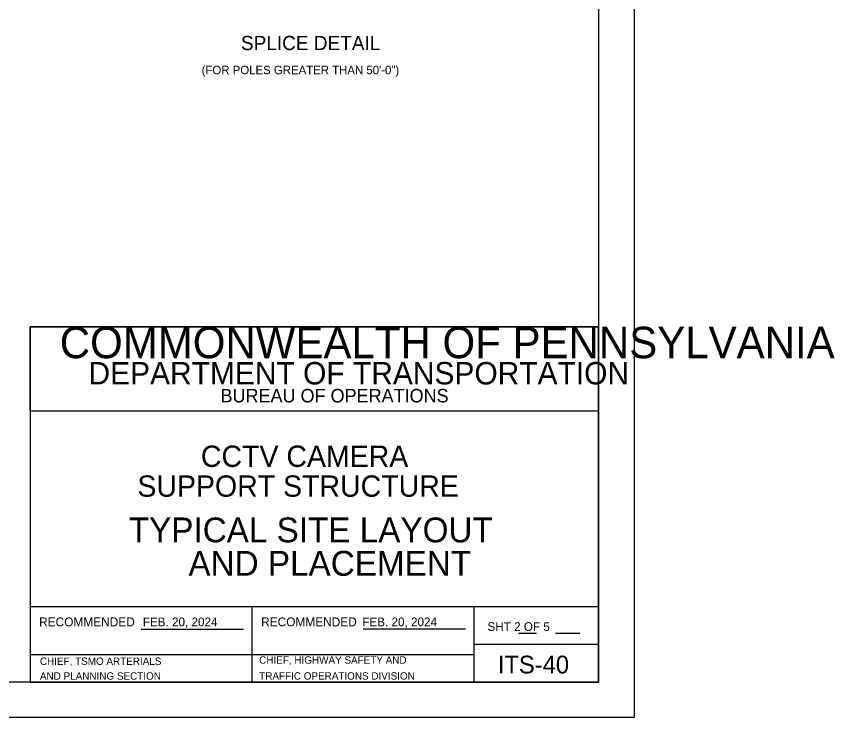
# Model space of a CAD drawing. Extents: x 1299104.8 to 1299141.6, y 239639.8 to 239661.8.
# Drawn here: x 1299130.11 to 1299141.62, y 239639.79 to 239649.66 of the extents above; entities that cross this region are included whole.
import ezdxf

# ---------------------------------------------------------------- set-up
doc = ezdxf.new("R2010")
doc.units = 0
for name, color, linetype in [('1', 7, 'Continuous'), ('2', 7, 'Continuous'), ('DIM TXT', 7, 'Continuous'), ('GS_plotshape_p', 7, 'Continuous'), ('Level 1', 7, 'Continuous'), ('PTEXT', 7, 'Continuous')]:
    doc.layers.add(name, color=color, linetype=linetype)

msp = doc.modelspace()

# ---------------------------------------------------------------- linework, layer by layer
at = {"layer": '1'}
for p, q in [((1299131.864, 239641.035), (1299133.302, 239641.035)), ((1299134.989, 239641.043), (1299136.427, 239641.043)), ((1299130.302, 239640.68), (1299133.427, 239640.68))]:
    msp.add_line(p, q, dxfattribs=at)
at = {"layer": 'DIM TXT'}
msp.add_line((1299138.802, 239639.791), (1299138.802, 239639.791), dxfattribs=at)
at = {"layer": 'GS_plotshape_p'}
msp.add_lwpolyline([(1299104.802, 239661.791), (1299138.802, 239661.791), (1299138.802, 239639.791), (1299104.802, 239639.791)], close=True, dxfattribs=at)
at = {"layer": 'Level 1'}
for p, q in [((1299130.302, 239641.354), (1299138.302, 239641.354)), ((1299133.427, 239640.291), (1299133.427, 239641.354)), ((1299136.552, 239640.291), (1299136.552, 239641.354)), ((1299137.177, 239640.979), (1299137.427, 239640.979)), ((1299137.694, 239640.981), (1299138.038, 239640.981)), ((1299136.552, 239640.823), (1299138.302, 239640.823)), ((1299133.427, 239640.68), (1299136.552, 239640.68))]:
    msp.add_line(p, q, dxfattribs=at)
for points in [[(1299138.302, 239640.291), (1299106.302, 239640.291), (1299106.302, 239661.291), (1299138.302, 239661.291)], [(1299130.302, 239640.291), (1299138.302, 239640.291), (1299138.302, 239645.291), (1299130.302, 239645.291)], [(1299130.302, 239645.291), (1299138.302, 239645.291), (1299138.302, 239644.104), (1299130.302, 239644.104)]]:
    msp.add_lwpolyline(points, close=True, dxfattribs=at)

# ---------------------------------------------------------------- texts
at = {"layer": '1'}
for s, height, p in [('COMMONWEALTH OF PENNSYLVANIA', 0.44223, (1299130.717, 239644.85)), ('DEPARTMENT OF TRANSPORTATION', 0.31514, (1299131.122, 239644.481)), ('BUREAU OF OPERATIONS', 0.18955, (1299132.98, 239644.228)), ('RECOMMENDED', 0.125, (1299130.427, 239641.076)), ('FEB. 20, 2024', 0.12303, (1299131.886, 239641.077)), ('RECOMMENDED', 0.125, (1299133.552, 239641.076)), ('FEB. 20, 2024', 0.12303, (1299134.976, 239641.077)), ('CHIEF, TSMO ARTERIALS ', 0.10417, (1299130.438, 239640.533)), ('CHIEF, HIGHWAY SAFETY AND ', 0.10417, (1299133.525, 239640.55)), ('TRAFFIC OPERATIONS DIVISION', 0.10417, (1299133.525, 239640.326)), ('AND PLANNING SECTION', 0.10417, (1299130.438, 239640.325))]:
    msp.add_text(s, height=height, dxfattribs=at).set_placement(p)
at = {"layer": '2'}
msp.add_text('SHT 2 OF 5', height=0.123, dxfattribs=at).set_placement((1299136.738, 239641.011))
at = {"layer": 'DIM TXT'}
for s, height, p in [('SPLICE DETAIL', 0.2, (1299133.268, 239649.186)), ('(FOR POLES GREATER THAN 50\'-0")', 0.12, (1299132.715, 239648.846))]:
    msp.add_text(s, height=height, dxfattribs=at).set_placement(p)
at = {"layer": 'PTEXT'}
for s, height, p in [('CCTV CAMERA', 0.3, (1299132.704, 239643.32)), ('SUPPORT STRUCTURE', 0.3, (1299131.81, 239642.9)), ('TYPICAL SITE LAYOUT', 0.35, (1299131.689, 239642.258)), ('AND PLACEMENT', 0.35, (1299132.529, 239641.788)), ('ITS-40', 0.25, (1299136.883, 239640.413))]:
    msp.add_text(s, height=height, dxfattribs=at).set_placement(p)

doc.saveas('drawing.dxf')
